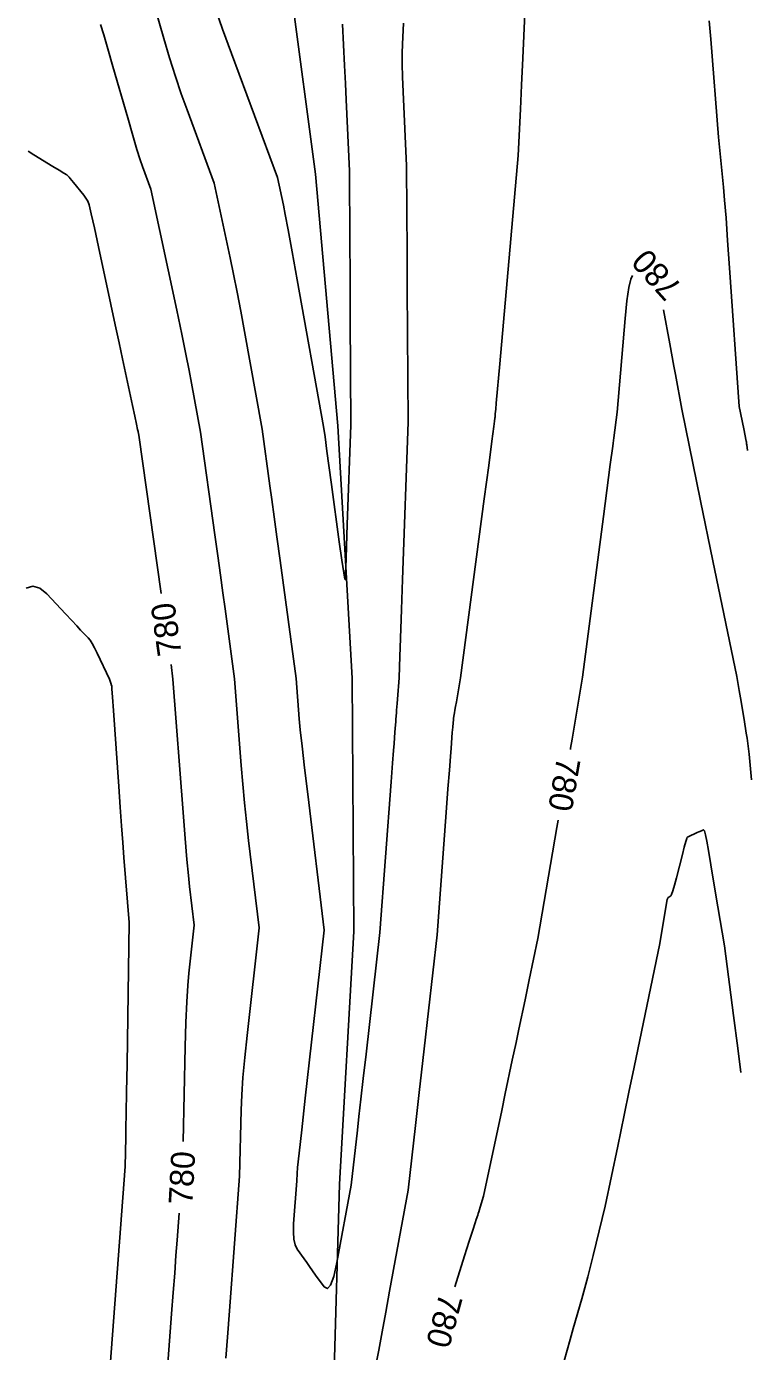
# Model space of a CAD drawing. Extents: x -26 to 1809989, y -25 to 828749.
# Drawn here: x 1809837.5 to 1809989, y 827618.3 to 827895.2 of the extents above; entities that cross this region are included whole.
import ezdxf

# ---------------------------------------------------------------- set-up
doc = ezdxf.new("R2010")
doc.units = 0
for name, color, linetype in [('DESIGN - CONTOURS - Index with Text', 7, 'Continuous'), ('DESIGN - CONTOURS - Intermediate with optional Text', 7, 'Continuous'), ('DESIGN - ROW - Slope Lines', 7, 'Continuous')]:
    doc.layers.add(name, color=color, linetype=linetype)

msp = doc.modelspace()

# ---------------------------------------------------------------- linework, layer by layer
at = {"layer": 'DESIGN - CONTOURS - Index with Text'}
for points in [[(1809865.63, 827776.73), (1809860.98, 827809.83), (1809860.96, 827809.94), (1809860.95, 827809.98), (1809860.94, 827810.05), (1809860.92, 827810.14), (1809860.82, 827810.61), (1809860.73, 827811.04), (1809860.5, 827812.1), (1809860.15, 827813.77), (1809859.66, 827816.05), (1809857.58, 827825.78), (1809856.87, 827829.1), (1809856.06, 827832.89), (1809855.15, 827837.16), (1809852.58, 827849.2), (1809851.71, 827853.19), (1809851.05, 827856.11), (1809850.58, 827857.96), (1809850.31, 827858.76), (1809849.51, 827859.97), (1809847.34, 827862.61), (1809846.62, 827863.49), (1809846.41, 827863.74), (1809846.3, 827863.87), (1809846.15, 827864.04), (1809845.92, 827864.21), (1809845.32, 827864.6), (1809844.36, 827865.19), (1809843.04, 827866), (1809839.04, 827868.44), (1809837.85, 827869.17)], [(1809964.13, 827843.21), (1809963.74, 827842.43), (1809963.35, 827840.67), (1809962.97, 827837.93), (1809962.6, 827834.22), (1809960.9, 827814.6), (1809960.21, 827809.27), (1809960.07, 827808.16), (1809959.98, 827807.54), (1809959.49, 827803.73), (1809958.07, 827792.85), (1809953.7, 827759.24), (1809952.07, 827749.65), (1809951.5, 827746.28), (1809951.18, 827744.42), (1809951.14, 827744.14)], [(1809988.98, 827737.8), (1809988.47, 827743.15), (1809988.36, 827744.29), (1809988.22, 827745.4), (1809988.07, 827746.5), (1809987.9, 827747.58), (1809987.42, 827750.44), (1809986.67, 827754.92), (1809986.41, 827756.44), (1809985.92, 827759.38), (1809980.92, 827783.59), (1809978.35, 827796.09), (1809974.4, 827815.25), (1809973.08, 827822.49), (1809972.76, 827824.23), (1809971.9, 827828.91), (1809970.58, 827836.05)], [(1809870.22, 827662.19), (1809870.68, 827681.98), (1809870.82, 827687.12), (1809870.99, 827691.41), (1809871.19, 827694.84), (1809871.42, 827697.41), (1809872.56, 827707.43), (1809871.57, 827715.53), (1809871.33, 827717.8), (1809871.02, 827721.13), (1809870.66, 827725.52), (1809870.23, 827730.97), (1809868.11, 827758.87), (1809867.7, 827761.87)], [(1809948.6, 827729.36), (1809948.33, 827727.82), (1809944.36, 827704.61), (1809942.56, 827696.03), (1809942.26, 827694.58), (1809941.96, 827693.19), (1809941.68, 827691.85), (1809940.38, 827685.66), (1809940.09, 827684.29), (1809939.8, 827682.91), (1809939.01, 827679.19), (1809937.55, 827672.26), (1809936.8, 827668.72), (1809933, 827650.78), (1809932.31, 827648.46), (1809932.17, 827647.98), (1809932.03, 827647.55), (1809931.9, 827647.16), (1809931.79, 827646.81), (1809931.48, 827645.94), (1809931.24, 827645.22), (1809930.75, 827643.71), (1809930.01, 827641.4), (1809929.03, 827638.3), (1809926.97, 827631.84)], [(1809858.86, 827547.81), (1809859.8, 827553.36), (1809862.18, 827572.38), (1809862.68, 827576.39), (1809863.17, 827580.29), (1809863.64, 827584.08), (1809866.22, 827604.57), (1809867.83, 827626.21), (1809868.17, 827630.65), (1809868.47, 827634.7), (1809868.74, 827638.36), (1809868.99, 827641.63), (1809869.41, 827647.21)]]:
    msp.add_lwpolyline(points, dxfattribs=at)
at = {"layer": 'DESIGN - CONTOURS - Intermediate with optional Text'}
for points in [[(1809942.71, 827922.88), (1809941.18, 827888.59), (1809940.93, 827882.94), (1809940.7, 827877.96), (1809940.26, 827868.28), (1809936.39, 827824.74), (1809935.66, 827816.54), (1809935.55, 827815.24), (1809935.46, 827814.29), (1809935.43, 827813.98), (1809935.41, 827813.75), (1809935.4, 827813.61), (1809935.4, 827813.57), (1809935.4, 827813.55), (1809935.4, 827813.54), (1809935.39, 827813.53), (1809935.39, 827813.51), (1809935.39, 827813.49), (1809935.38, 827813.38), (1809935.3, 827812.76), (1809935.15, 827811.65), (1809934.74, 827808.56), (1809934.07, 827803.51), (1809933.14, 827796.49), (1809928.2, 827759.13), (1809927.33, 827754.12), (1809927.16, 827753.15), (1809927.03, 827752.38), (1809926.93, 827751.81), (1809926.87, 827751.44), (1809926.74, 827750.72), (1809926.69, 827750.32), (1809926.62, 827749.69), (1809926.55, 827748.82), (1809926.46, 827747.7), (1809926.21, 827744.4), (1809926.08, 827742.64), (1809925.87, 827739.81), (1809925.57, 827735.93), (1809925.2, 827730.98), (1809923.28, 827705.44), (1809920.58, 827681.55), (1809920.04, 827676.71), (1809919.55, 827672.43), (1809919.13, 827668.71), (1809918.77, 827665.54), (1809917.25, 827652.08), (1809913.36, 827630.94), (1809912.55, 827626.55), (1809911.8, 827622.45), (1809911.1, 827618.64), (1809910.45, 827615.12)], [(1809916.24, 827895.9), (1809916.04, 827891.51), (1809915.99, 827889.65), (1809916, 827887.38), (1809916.07, 827884.7), (1809916.2, 827881.59), (1809916.92, 827866.14), (1809916.97, 827856.67), (1809916.99, 827854.14), (1809917.01, 827850.62), (1809917.04, 827846.1), (1809917.07, 827840.58), (1809917.25, 827812.52), (1809916.08, 827779.66), (1809915.86, 827773.37), (1809915.57, 827765.36), (1809915.51, 827763.63), (1809915.35, 827759.08), (1809915.02, 827754.67), (1809914.95, 827753.78), (1809914.84, 827752.34), (1809914.8, 827751.8), (1809914.7, 827750.48), (1809914.66, 827749.94), (1809914.61, 827749.31), (1809914.49, 827747.75), (1809914.32, 827745.41), (1809914.2, 827743.94), (1809914, 827741.27), (1809913.71, 827737.4), (1809911.32, 827705.91), (1809908.44, 827680.45), (1809907.86, 827675.36), (1809907.37, 827671.03), (1809906.96, 827667.44), (1809906.64, 827664.6), (1809905.33, 827653.07), (1809902.35, 827636.91), (1809901.71, 827634), (1809901.05, 827632.18), (1809900.39, 827631.47), (1809899.72, 827631.84), (1809897.92, 827634.31), (1809897.26, 827635.22), (1809896.64, 827636.08), (1809896.06, 827636.9), (1809895.51, 827637.68), (1809894.09, 827639.69), (1809893.64, 827640.59), (1809893.36, 827641.78), (1809893.26, 827643.26), (1809893.32, 827645.04), (1809893.99, 827654.01), (1809894.03, 827655.55), (1809894.14, 827656.78), (1809894.47, 827659.81), (1809895, 827664.64), (1809895.75, 827671.26), (1809899.73, 827706.36), (1809896.26, 827734.77), (1809895.59, 827740.32), (1809895.08, 827744.81), (1809894.71, 827748.22), (1809894.5, 827750.56), (1809893.86, 827758.98), (1809890.51, 827783.61), (1809889.84, 827788.55), (1809889.26, 827792.79), (1809888.77, 827796.36), (1809888.37, 827799.23), (1809886.71, 827811.06), (1809883.04, 827831.49), (1809882.27, 827835.73), (1809881.51, 827839.72), (1809880.77, 827843.44), (1809880.05, 827846.91), (1809876.72, 827862.46), (1809871.04, 827877.79), (1809869.83, 827881.18), (1809868.61, 827884.81), (1809867.4, 827888.67), (1809866.19, 827892.75), (1809860.54, 827912.33)], [(1809903.56, 827895.75), (1809903.97, 827887.09), (1809904.14, 827883.32), (1809904.3, 827879.94), (1809904.98, 827865.05), (1809905.06, 827850.31), (1809905.1, 827843.17), (1809905.13, 827838.98), (1809905.15, 827834.38), (1809905.28, 827811.94), (1809904.53, 827791.16), (1809904.28, 827784.2), (1809904.21, 827782.19), (1809904.17, 827781.14), (1809904.12, 827779.66), (1809904.03, 827779.74), (1809903.79, 827781.08), (1809903.4, 827783.68), (1809902.86, 827787.54), (1809901.23, 827799.52), (1809900.69, 827803.52), (1809900.28, 827806.5), (1809899.88, 827809.46), (1809899.57, 827811.67), (1809894.08, 827842.26), (1809893.02, 827848.15), (1809892.19, 827852.71), (1809891.58, 827855.95), (1809891.2, 827857.86), (1809889.96, 827863.67), (1809880.36, 827889.57), (1809878.49, 827894.68), (1809876.99, 827898.89)], [(1809879.16, 827616.92), (1809879.49, 827621.35), (1809879.91, 827626.85), (1809882.03, 827655), (1809882.35, 827668.77), (1809882.48, 827671.95), (1809882.73, 827675.61), (1809883.1, 827679.74), (1809883.59, 827684.34), (1809886.14, 827706.89), (1809883.91, 827725.15), (1809883.46, 827729.06), (1809883.05, 827732.97), (1809882.69, 827736.87), (1809882.37, 827740.76), (1809880.98, 827758.93), (1809879, 827773.55), (1809878.54, 827776.87), (1809878.03, 827780.55), (1809877.47, 827784.6), (1809876.85, 827789.01), (1809873.84, 827810.44), (1809872, 827820.71), (1809871.51, 827823.32), (1809870.83, 827826.73), (1809869.96, 827830.94), (1809868.9, 827835.96), (1809863.49, 827861.25), (1809861.73, 827866), (1809861.25, 827867.4), (1809860.58, 827869.55), (1809859.71, 827872.45), (1809858.65, 827876.11), (1809855.54, 827886.88), (1809854.48, 827890.54), (1809853.63, 827893.46), (1809852.99, 827895.64)], [(1809988.13, 827806.63), (1809987.99, 827807.81), (1809987.96, 827808.04), (1809987.94, 827808.24), (1809987.91, 827808.42), (1809987.88, 827808.55), (1809987.35, 827811.13), (1809986.38, 827815.82), (1809984.4, 827844.8), (1809984, 827850.51), (1809983.66, 827855.23), (1809983.36, 827858.96), (1809983.11, 827861.68), (1809982.07, 827872.1), (1809980.48, 827892.6), (1809980.13, 827896.45)], [(1809854.31, 827606.08), (1809858.12, 827656.98), (1809858.26, 827663.02), (1809858.29, 827664.94), (1809858.35, 827668.13), (1809858.42, 827672.59), (1809858.51, 827678.31), (1809858.97, 827707.96), (1809857.87, 827721.6), (1809857.63, 827724.72), (1809857.37, 827728.22), (1809857.08, 827732.12), (1809856.78, 827736.41), (1809855.68, 827752.29), (1809855.48, 827755.1), (1809855.36, 827756.81), (1809855.31, 827757.41), (1809855.22, 827757.68), (1809855.18, 827757.81), (1809855.13, 827757.97), (1809854.86, 827758.82), (1809852.27, 827764.3), (1809851.73, 827765.37), (1809851.24, 827766.26), (1809850.79, 827766.96), (1809850.37, 827767.46), (1809849.33, 827768.55), (1809848.8, 827769.11), (1809848.01, 827769.95), (1809846.95, 827771.09), (1809845.63, 827772.51), (1809841.73, 827776.69), (1809840.28, 827777.87), (1809838.85, 827778.25), (1809837.45, 827777.85)], [(1809986.78, 827676.66), (1809986.12, 827681.73), (1809985.24, 827688.53), (1809983.35, 827703.08), (1809981.98, 827711.28), (1809981, 827717.07), (1809980, 827723.02), (1809979.65, 827724.96), (1809979.37, 827726.33), (1809979.15, 827727.14), (1809978.99, 827727.37), (1809978.66, 827727.23), (1809978.51, 827727.16), (1809977.98, 827726.93), (1809977.62, 827726.76), (1809975.75, 827725.9), (1809975.55, 827725.81), (1809975.46, 827725.57), (1809975.26, 827724.88), (1809974.95, 827723.74), (1809974.54, 827722.16), (1809973.31, 827717.35), (1809972.89, 827715.76), (1809972.55, 827714.59), (1809972.29, 827713.86), (1809972.1, 827713.55), (1809971.71, 827713.3), (1809971.58, 827713.2), (1809971.48, 827713.08), (1809971.41, 827712.94), (1809971.37, 827712.79), (1809971.24, 827712.05), (1809969.81, 827703.61), (1809964.46, 827677.75), (1809963.38, 827672.56), (1809962.46, 827668.08), (1809961.67, 827664.32), (1809961.04, 827661.26), (1809958.41, 827648.67), (1809955.91, 827638.38), (1809955.35, 827636.16), (1809954.77, 827633.91), (1809954.15, 827631.63), (1809953.51, 827629.32), (1809951.73, 827623.13), (1809951.08, 827620.83), (1809950.46, 827618.59), (1809949.86, 827616.4)]]:
    msp.add_lwpolyline(points, dxfattribs=at)
at = {"layer": 'DESIGN - ROW - Slope Lines'}
for p, q in [((1809897.86, 827864.4), (1809890.99, 827916.24)), ((1809902.52, 827811.81), (1809897.86, 827864.4)), ((1809905.54, 827759.04), (1809902.52, 827811.81)), ((1809905.9, 827706.12), (1809905.54, 827759.04)), ((1809902.93, 827653.27), (1809905.9, 827706.12)), ((1809901.36, 827600.12), (1809902.93, 827653.27))]:
    msp.add_line(p, q, dxfattribs=at)

# ---------------------------------------------------------------- texts
at = {"layer": 'DESIGN - CONTOURS - Index with Text'}
for rotation, p in [(132.0045, (1809974.75, 827840.87)), (97.9347, (1809869.93, 827764.04)), (260.2643, (1809948.36, 827742.75)), (86.9178, (1809872.17, 827648.91)), (254.7625, (1809923.86, 827630.78))]:
    msp.add_text('780', height=5, rotation=rotation, dxfattribs=at).set_placement(p)

doc.saveas('drawing.dxf')
